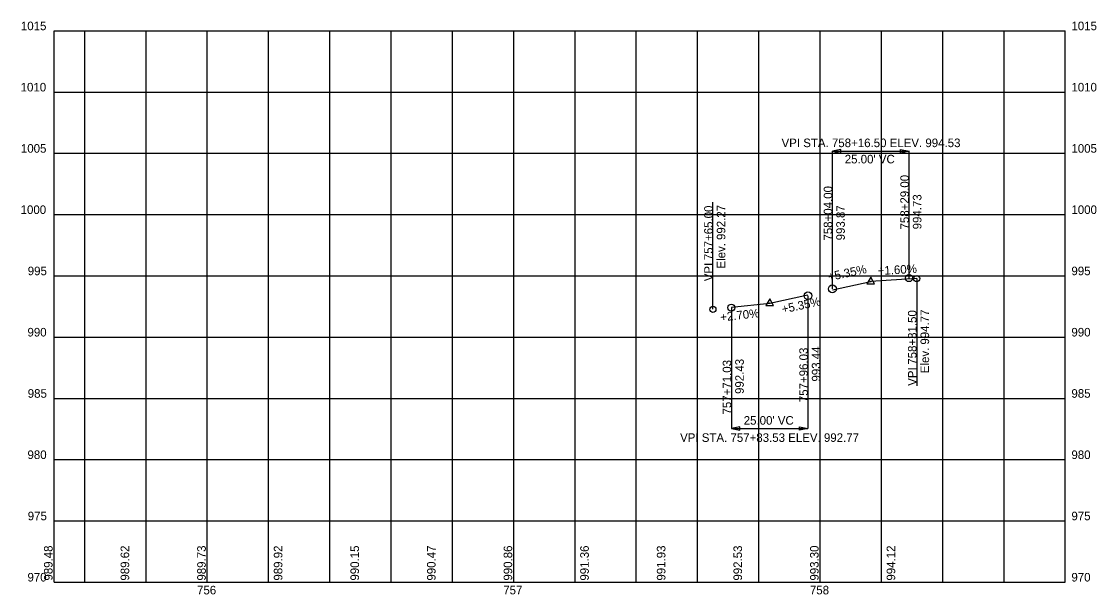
# Model space of a CAD drawing. Extents: x 539 to 890, y 966 to 1153.
import ezdxf

# ---------------------------------------------------------------- set-up
doc = ezdxf.new("R2010")
doc.units = 0
for name, color, linetype in [('PF_P_Sta_Elev_Text', 7, 'Continuous'), ('PF_P_Text', 7, 'Continuous'), ('PF_X_Text_Strip_Grade', 7, 'Continuous'), ('RW_X_Esmt_SC', 7, 'Continuous'), ('SC_Scratch9', 7, 'Continuous'), ('UT_X_Misc_Cells', 7, 'Continuous'), ('UT_X_Water', 7, 'Continuous')]:
    doc.layers.add(name, color=color, linetype=linetype)

msp = doc.modelspace()

# ---------------------------------------------------------------- linework, layer by layer
at = {"layer": 'PF_P_Text'}
for points in [[(816.5, 1069.58), (815.25, 1067.42), (817.75, 1067.42)], [(783.53, 1062.52), (782.28, 1060.36), (784.78, 1060.36)]]:
    msp.add_lwpolyline(points, close=True, dxfattribs=at)
at = {"layer": 'RW_X_Esmt_SC'}
for centre in [(816.5, 1068.14), (783.53, 1061.08)]:
    msp.add_circle(centre, 0.1, dxfattribs=at)
at = {"layer": 'SC_Scratch9'}
for p, q in [((804, 1065.75), (804, 1110.66)), ((829, 1069.28), (829, 1110.66)), ((765, 1059.08), (765, 1094.08)), ((831.5, 1069.1), (831.5, 1034.1)), ((796.03, 1063.52), (796.03, 1020.19)), ((771.03, 1059.61), (771.03, 1020.19))]:
    msp.add_line(p, q, dxfattribs=at)
for centre, radius in [((829, 1069.28), 1.18), ((831.5, 1069.1), 1), ((804, 1065.75), 1.28), ((796.03, 1063.52), 1.24), ((765, 1059.08), 1), ((771.03, 1059.61), 1.13)]:
    msp.add_circle(centre, radius, dxfattribs=at)
at = {"layer": 'UT_X_Misc_Cells'}
for p, q in [((550, 1150), (880, 1150)), ((550, 970), (550, 1150)), ((560, 970), (560, 1150)), ((580, 970), (580, 1150)), ((600, 970), (600, 1150)), ((620, 970), (620, 1150)), ((640, 970), (640, 1150)), ((660, 970), (660, 1150)), ((680, 970), (680, 1150)), ((700, 970), (700, 1150)), ((720, 970), (720, 1150)), ((740, 970), (740, 1150)), ((760, 970), (760, 1150)), ((780, 970), (780, 1150)), ((800, 970), (800, 1150)), ((820, 970), (820, 1150)), ((840, 970), (840, 1150)), ((860, 970), (860, 1150)), ((880, 970), (880, 1150)), ((880, 970), (880, 1150)), ((550, 1130), (880, 1130)), ((550, 1110), (880, 1110)), ((550, 1090), (880, 1090)), ((550, 1070), (880, 1070)), ((550, 1050), (880, 1050)), ((550, 1030), (880, 1030)), ((550, 1010), (880, 1010)), ((550, 990), (880, 990)), ((550, 970), (880, 970))]:
    msp.add_line(p, q, dxfattribs=at)
at = {"layer": 'UT_X_Water'}
for p, q in [((804, 1110.66), (829, 1110.66)), ((804, 1065.46), (816.5, 1068.14)), ((831.5, 1069.1), (816.5, 1068.14)), ((783.53, 1061.08), (796.03, 1063.76)), ((771.03, 1059.73), (783.53, 1061.08)), ((771.03, 1020.19), (796.03, 1020.19))]:
    msp.add_line(p, q, dxfattribs=at)
for points in [[(806.8, 1110.1), (806.8, 1111.22), (804, 1110.66)], [(826.2, 1110.1), (826.2, 1111.22), (829, 1110.66)], [(773.83, 1019.63), (773.83, 1020.75), (771.03, 1020.19)], [(793.23, 1019.63), (793.23, 1020.75), (796.03, 1020.19)]]:
    msp.add_lwpolyline(points, close=True, dxfattribs=at)

# ---------------------------------------------------------------- texts
at = {"layer": 'PF_P_Sta_Elev_Text'}
for s, p in [('1015', (539.16, 1150.2)), ('1015', (882, 1150.2)), ('1010', (539.07, 1130.2)), ('1010', (882, 1130.2)), ('1005', (539.16, 1110.2)), ('1005', (882, 1110.2)), ('1000', (539.07, 1090.2)), ('1000', (882, 1090.2)), ('995', (541.39, 1070.2)), ('995', (882, 1070.2)), ('990', (541.31, 1050.2)), ('990', (882, 1050.2)), ('985', (541.39, 1030.2)), ('985', (882, 1030.2)), ('980', (541.31, 1010.2)), ('980', (882, 1010.2)), ('975', (541.39, 990.2)), ('975', (882, 990.2)), ('970', (541.31, 970.2)), ('970', (882, 970.2)), ('756', (596.64, 966)), ('757', (696.58, 966)), ('758', (796.66, 966))]:
    msp.add_text(s, height=2.8, dxfattribs=at).set_placement(p)
at = {"layer": 'PF_X_Text_Strip_Grade'}
for s, p in [('989.48', (549.5, 970.5)), ('989.62', (574.5, 970.5)), ('989.73', (599.5, 970.5)), ('989.92', (624.5, 970.5)), ('990.15', (649.5, 970.5)), ('990.47', (674.5, 970.5)), ('990.86', (699.5, 970.5)), ('991.36', (724.5, 970.5)), ('991.93', (749.5, 970.5)), ('992.53', (774.5, 970.5)), ('993.30', (799.5, 970.5)), ('994.12', (824.5, 970.5))]:
    msp.add_text(s, height=2.8, rotation=90, dxfattribs=at).set_placement(p)
at = {"layer": 'RW_X_Esmt_SC'}
for s, rotation, p in [('+5.35%', 12.0813, (802.84, 1068.26)), ('+1.60%', 3.2814, (818.85, 1070.24)), ('+5.35%', 12.0813, (787.79, 1057.7)), ('+2.70%', 6.3029, (767.54, 1055.09))]:
    msp.add_text(s, height=2.8, rotation=rotation, dxfattribs=at).set_placement(p)
at = {"layer": 'SC_Scratch9'}
for s, p in [('758+29.00', (828.96, 1085.15)), ('758+04.00', (803.96, 1081.52)), ('994.73', (833.05, 1085.17)), ('757+65.00', (764.96, 1075.13)), ('992.27', (769.05, 1081.7)), ('993.87', (808.05, 1081.58)), ('Elev. ', (769.05, 1072.38)), ('VPI ', (764.96, 1068.24)), ('758+31.50', (831.46, 1040.99)), ('994.77', (835.55, 1047.54)), ('757+96.03', (795.99, 1028.76)), ('993.44', (800.08, 1035.49)), ('Elev. ', (835.55, 1038.22)), ('757+71.03', (770.99, 1024.73)), ('992.43', (775.08, 1031.43)), ('VPI ', (831.46, 1034.1))]:
    msp.add_text(s, height=2.8, rotation=90, dxfattribs=at).set_placement(p)
at = {"layer": 'UT_X_Water'}
for s, p in [('VPI STA. 758+16.50 ELEV. 994.53', (787.4, 1112.02)), ("25.00' VC", (808.02, 1106.71)), ("25.00' VC", (775.05, 1021.4)), ('VPI STA. 757+83.53 ELEV. 992.77', (754.29, 1015.79))]:
    msp.add_text(s, height=2.8, dxfattribs=at).set_placement(p)

doc.saveas('drawing.dxf')
